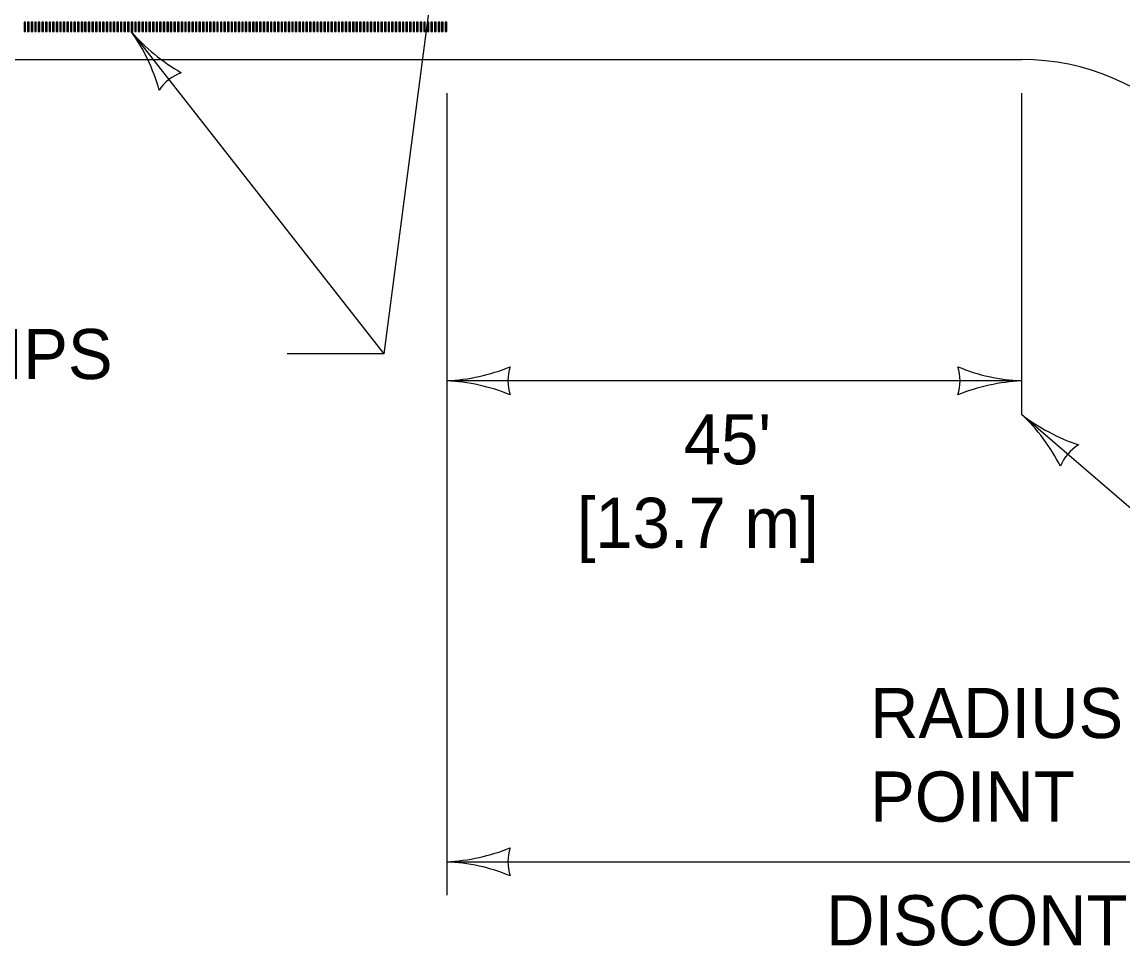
# Model space of a CAD drawing. Extents: x 49991.4 to 50021, y 49987.6 to 50011.4.
# Drawn here: x 50005.772 to 50007.091, y 49993.098 to 49994.204 of the extents above; entities that cross this region are included whole.
import ezdxf

# ---------------------------------------------------------------- set-up
doc = ezdxf.new("R2010")
doc.units = 0
for name, color, linetype in [('Level 1', 7, 'Continuous'), ('Level 2', 7, 'Continuous'), ('Level 3', 7, 'Continuous')]:
    doc.layers.add(name, color=color, linetype=linetype)

msp = doc.modelspace()

# ---------------------------------------------------------------- linework, layer by layer
at = {"layer": 'Level 1'}
msp.add_line((50005.3299, 49994.1595), (50006.9691, 49994.1595), dxfattribs=at)
for points in [[(50005.7764, 49994.2045), (50005.7745, 49994.2045), (50005.7745, 49994.1933), (50005.7764, 49994.1933)], [(50005.7807, 49994.2045), (50005.7787, 49994.2045), (50005.7787, 49994.1933), (50005.7807, 49994.1933)], [(50005.7849, 49994.2045), (50005.783, 49994.2045), (50005.783, 49994.1933), (50005.7849, 49994.1933)], [(50005.7892, 49994.2045), (50005.7873, 49994.2045), (50005.7873, 49994.1933), (50005.7892, 49994.1933)], [(50005.7935, 49994.2045), (50005.7916, 49994.2045), (50005.7916, 49994.1933), (50005.7935, 49994.1933)], [(50005.7977, 49994.2045), (50005.7959, 49994.2045), (50005.7959, 49994.1933), (50005.7977, 49994.1933)], [(50005.802, 49994.2045), (50005.8001, 49994.2045), (50005.8001, 49994.1933), (50005.802, 49994.1933)], [(50005.8063, 49994.2045), (50005.8044, 49994.2045), (50005.8044, 49994.1933), (50005.8063, 49994.1933)], [(50005.8106, 49994.2045), (50005.8087, 49994.2045), (50005.8087, 49994.1933), (50005.8106, 49994.1933)], [(50005.8149, 49994.2045), (50005.8129, 49994.2045), (50005.8129, 49994.1933), (50005.8149, 49994.1933)], [(50005.8191, 49994.2045), (50005.8172, 49994.2045), (50005.8172, 49994.1933), (50005.8191, 49994.1933)], [(50005.8234, 49994.2045), (50005.8215, 49994.2045), (50005.8215, 49994.1933), (50005.8234, 49994.1933)], [(50005.8277, 49994.2045), (50005.8258, 49994.2045), (50005.8258, 49994.1933), (50005.8277, 49994.1933)], [(50005.8319, 49994.2045), (50005.8301, 49994.2045), (50005.8301, 49994.1933), (50005.8319, 49994.1933)], [(50005.8362, 49994.2045), (50005.8343, 49994.2045), (50005.8343, 49994.1933), (50005.8362, 49994.1933)], [(50005.8405, 49994.2045), (50005.8386, 49994.2045), (50005.8386, 49994.1933), (50005.8405, 49994.1933)], [(50005.8448, 49994.2045), (50005.8429, 49994.2045), (50005.8429, 49994.1933), (50005.8448, 49994.1933)], [(50005.8491, 49994.2045), (50005.8471, 49994.2045), (50005.8471, 49994.1933), (50005.8491, 49994.1933)], [(50005.8533, 49994.2045), (50005.8514, 49994.2045), (50005.8514, 49994.1933), (50005.8533, 49994.1933)], [(50005.8576, 49994.2045), (50005.8557, 49994.2045), (50005.8557, 49994.1933), (50005.8576, 49994.1933)], [(50005.8619, 49994.2045), (50005.86, 49994.2045), (50005.86, 49994.1933), (50005.8619, 49994.1933)], [(50005.8661, 49994.2045), (50005.8643, 49994.2045), (50005.8643, 49994.1933), (50005.8661, 49994.1933)], [(50005.8704, 49994.2045), (50005.8685, 49994.2045), (50005.8685, 49994.1933), (50005.8704, 49994.1933)], [(50005.8747, 49994.2045), (50005.8728, 49994.2045), (50005.8728, 49994.1933), (50005.8747, 49994.1933)], [(50005.879, 49994.2045), (50005.8771, 49994.2045), (50005.8771, 49994.1933), (50005.879, 49994.1933)], [(50005.8833, 49994.2045), (50005.8813, 49994.2045), (50005.8813, 49994.1933), (50005.8833, 49994.1933)], [(50005.8875, 49994.2045), (50005.8856, 49994.2045), (50005.8856, 49994.1933), (50005.8875, 49994.1933)], [(50005.8918, 49994.2045), (50005.8899, 49994.2045), (50005.8899, 49994.1933), (50005.8918, 49994.1933)], [(50005.8961, 49994.2045), (50005.8942, 49994.2045), (50005.8942, 49994.1933), (50005.8961, 49994.1933)], [(50005.9003, 49994.2045), (50005.8985, 49994.2045), (50005.8985, 49994.1933), (50005.9003, 49994.1933)], [(50005.9046, 49994.2045), (50005.9027, 49994.2045), (50005.9027, 49994.1933), (50005.9046, 49994.1933)], [(50005.9089, 49994.2045), (50005.907, 49994.2045), (50005.907, 49994.1933), (50005.9089, 49994.1933)], [(50005.9132, 49994.2045), (50005.9113, 49994.2045), (50005.9113, 49994.1933), (50005.9132, 49994.1933)], [(50005.9175, 49994.2045), (50005.9155, 49994.2045), (50005.9155, 49994.1933), (50005.9175, 49994.1933)], [(50005.9217, 49994.2045), (50005.9198, 49994.2045), (50005.9198, 49994.1933), (50005.9217, 49994.1933)], [(50005.926, 49994.2045), (50005.9241, 49994.2045), (50005.9241, 49994.1933), (50005.926, 49994.1933)], [(50005.9303, 49994.2045), (50005.9284, 49994.2045), (50005.9284, 49994.1933), (50005.9303, 49994.1933)], [(50005.9345, 49994.2045), (50005.9327, 49994.2045), (50005.9327, 49994.1933), (50005.9345, 49994.1933)], [(50005.9388, 49994.2045), (50005.9369, 49994.2045), (50005.9369, 49994.1933), (50005.9388, 49994.1933)], [(50005.9431, 49994.2045), (50005.9412, 49994.2045), (50005.9412, 49994.1933), (50005.9431, 49994.1933)], [(50005.9474, 49994.2045), (50005.9455, 49994.2045), (50005.9455, 49994.1933), (50005.9474, 49994.1933)], [(50005.9517, 49994.2045), (50005.9497, 49994.2045), (50005.9497, 49994.1933), (50005.9517, 49994.1933)], [(50005.9559, 49994.2045), (50005.954, 49994.2045), (50005.954, 49994.1933), (50005.9559, 49994.1933)], [(50005.9602, 49994.2045), (50005.9583, 49994.2045), (50005.9583, 49994.1933), (50005.9602, 49994.1933)], [(50005.9645, 49994.2045), (50005.9626, 49994.2045), (50005.9626, 49994.1933), (50005.9645, 49994.1933)], [(50005.9687, 49994.2045), (50005.9669, 49994.2045), (50005.9669, 49994.1933), (50005.9687, 49994.1933)], [(50005.973, 49994.2045), (50005.9711, 49994.2045), (50005.9711, 49994.1933), (50005.973, 49994.1933)], [(50005.9773, 49994.2045), (50005.9754, 49994.2045), (50005.9754, 49994.1933), (50005.9773, 49994.1933)], [(50005.9816, 49994.2045), (50005.9797, 49994.2045), (50005.9797, 49994.1933), (50005.9816, 49994.1933)], [(50005.9859, 49994.2045), (50005.9839, 49994.2045), (50005.9839, 49994.1933), (50005.9859, 49994.1933)], [(50005.9901, 49994.2045), (50005.9882, 49994.2045), (50005.9882, 49994.1933), (50005.9901, 49994.1933)], [(50005.9944, 49994.2045), (50005.9925, 49994.2045), (50005.9925, 49994.1933), (50005.9944, 49994.1933)], [(50005.9987, 49994.2045), (50005.9968, 49994.2045), (50005.9968, 49994.1933), (50005.9987, 49994.1933)], [(50006.0029, 49994.2045), (50006.0011, 49994.2045), (50006.0011, 49994.1933), (50006.0029, 49994.1933)], [(50006.0072, 49994.2045), (50006.0053, 49994.2045), (50006.0053, 49994.1933), (50006.0072, 49994.1933)], [(50006.0115, 49994.2045), (50006.0096, 49994.2045), (50006.0096, 49994.1933), (50006.0115, 49994.1933)], [(50006.0158, 49994.2045), (50006.0139, 49994.2045), (50006.0139, 49994.1933), (50006.0158, 49994.1933)], [(50006.0201, 49994.2045), (50006.0181, 49994.2045), (50006.0181, 49994.1933), (50006.0201, 49994.1933)], [(50006.0243, 49994.2045), (50006.0224, 49994.2045), (50006.0224, 49994.1933), (50006.0243, 49994.1933)], [(50006.0286, 49994.2045), (50006.0267, 49994.2045), (50006.0267, 49994.1933), (50006.0286, 49994.1933)], [(50006.0329, 49994.2045), (50006.031, 49994.2045), (50006.031, 49994.1933), (50006.0329, 49994.1933)], [(50006.0371, 49994.2045), (50006.0353, 49994.2045), (50006.0353, 49994.1933), (50006.0371, 49994.1933)], [(50006.0414, 49994.2045), (50006.0395, 49994.2045), (50006.0395, 49994.1933), (50006.0414, 49994.1933)], [(50006.0457, 49994.2045), (50006.0438, 49994.2045), (50006.0438, 49994.1933), (50006.0457, 49994.1933)], [(50006.05, 49994.2045), (50006.0481, 49994.2045), (50006.0481, 49994.1933), (50006.05, 49994.1933)], [(50006.0543, 49994.2045), (50006.0523, 49994.2045), (50006.0523, 49994.1933), (50006.0543, 49994.1933)], [(50006.0585, 49994.2045), (50006.0566, 49994.2045), (50006.0566, 49994.1933), (50006.0585, 49994.1933)], [(50006.0628, 49994.2045), (50006.0609, 49994.2045), (50006.0609, 49994.1933), (50006.0628, 49994.1933)], [(50006.0671, 49994.2045), (50006.0652, 49994.2045), (50006.0652, 49994.1933), (50006.0671, 49994.1933)], [(50006.0713, 49994.2045), (50006.0695, 49994.2045), (50006.0695, 49994.1933), (50006.0713, 49994.1933)], [(50006.0756, 49994.2045), (50006.0737, 49994.2045), (50006.0737, 49994.1933), (50006.0756, 49994.1933)], [(50006.0799, 49994.2045), (50006.078, 49994.2045), (50006.078, 49994.1933), (50006.0799, 49994.1933)], [(50006.0842, 49994.2045), (50006.0823, 49994.2045), (50006.0823, 49994.1933), (50006.0842, 49994.1933)], [(50006.0885, 49994.2045), (50006.0865, 49994.2045), (50006.0865, 49994.1933), (50006.0885, 49994.1933)], [(50006.0927, 49994.2045), (50006.0908, 49994.2045), (50006.0908, 49994.1933), (50006.0927, 49994.1933)], [(50006.097, 49994.2045), (50006.0951, 49994.2045), (50006.0951, 49994.1933), (50006.097, 49994.1933)], [(50006.1013, 49994.2045), (50006.0994, 49994.2045), (50006.0994, 49994.1933), (50006.1013, 49994.1933)], [(50006.1055, 49994.2045), (50006.1037, 49994.2045), (50006.1037, 49994.1933), (50006.1055, 49994.1933)], [(50006.1098, 49994.2045), (50006.1079, 49994.2045), (50006.1079, 49994.1933), (50006.1098, 49994.1933)], [(50006.1141, 49994.2045), (50006.1122, 49994.2045), (50006.1122, 49994.1933), (50006.1141, 49994.1933)], [(50006.1184, 49994.2045), (50006.1165, 49994.2045), (50006.1165, 49994.1933), (50006.1184, 49994.1933)], [(50006.1227, 49994.2045), (50006.1207, 49994.2045), (50006.1207, 49994.1933), (50006.1227, 49994.1933)], [(50006.1269, 49994.2045), (50006.125, 49994.2045), (50006.125, 49994.1933), (50006.1269, 49994.1933)], [(50006.1312, 49994.2045), (50006.1293, 49994.2045), (50006.1293, 49994.1933), (50006.1312, 49994.1933)], [(50006.1355, 49994.2045), (50006.1335, 49994.2045), (50006.1335, 49994.1933), (50006.1355, 49994.1933)], [(50006.1397, 49994.2045), (50006.1378, 49994.2045), (50006.1378, 49994.1933), (50006.1397, 49994.1933)], [(50006.144, 49994.2045), (50006.1421, 49994.2045), (50006.1421, 49994.1933), (50006.144, 49994.1933)], [(50006.1483, 49994.2045), (50006.1464, 49994.2045), (50006.1464, 49994.1933), (50006.1483, 49994.1933)], [(50006.1525, 49994.2045), (50006.1507, 49994.2045), (50006.1507, 49994.1933), (50006.1525, 49994.1933)], [(50006.1568, 49994.2045), (50006.1549, 49994.2045), (50006.1549, 49994.1933), (50006.1568, 49994.1933)], [(50006.1611, 49994.2045), (50006.1592, 49994.2045), (50006.1592, 49994.1933), (50006.1611, 49994.1933)], [(50006.1654, 49994.2045), (50006.1635, 49994.2045), (50006.1635, 49994.1933), (50006.1654, 49994.1933)], [(50006.1697, 49994.2045), (50006.1677, 49994.2045), (50006.1677, 49994.1933), (50006.1697, 49994.1933)], [(50006.1739, 49994.2045), (50006.172, 49994.2045), (50006.172, 49994.1933), (50006.1739, 49994.1933)], [(50006.1782, 49994.2045), (50006.1763, 49994.2045), (50006.1763, 49994.1933), (50006.1782, 49994.1933)], [(50006.1825, 49994.2045), (50006.1806, 49994.2045), (50006.1806, 49994.1933), (50006.1825, 49994.1933)], [(50006.1867, 49994.2045), (50006.1849, 49994.2045), (50006.1849, 49994.1933), (50006.1867, 49994.1933)], [(50006.191, 49994.2045), (50006.1891, 49994.2045), (50006.1891, 49994.1933), (50006.191, 49994.1933)], [(50006.1953, 49994.2045), (50006.1934, 49994.2045), (50006.1934, 49994.1933), (50006.1953, 49994.1933)], [(50006.1996, 49994.2045), (50006.1977, 49994.2045), (50006.1977, 49994.1933), (50006.1996, 49994.1933)], [(50006.2039, 49994.2045), (50006.2019, 49994.2045), (50006.2019, 49994.1933), (50006.2039, 49994.1933)], [(50006.2081, 49994.2045), (50006.2062, 49994.2045), (50006.2062, 49994.1933), (50006.2081, 49994.1933)], [(50006.2124, 49994.2045), (50006.2105, 49994.2045), (50006.2105, 49994.1933), (50006.2124, 49994.1933)], [(50006.2167, 49994.2045), (50006.2148, 49994.2045), (50006.2148, 49994.1933), (50006.2167, 49994.1933)], [(50006.2209, 49994.2045), (50006.2191, 49994.2045), (50006.2191, 49994.1933), (50006.2209, 49994.1933)], [(50006.2252, 49994.2045), (50006.2233, 49994.2045), (50006.2233, 49994.1933), (50006.2252, 49994.1933)], [(50006.2295, 49994.2045), (50006.2276, 49994.2045), (50006.2276, 49994.1933), (50006.2295, 49994.1933)], [(50006.2338, 49994.2045), (50006.2319, 49994.2045), (50006.2319, 49994.1933), (50006.2338, 49994.1933)], [(50006.2381, 49994.2045), (50006.2361, 49994.2045), (50006.2361, 49994.1933), (50006.2381, 49994.1933)], [(50006.2423, 49994.2045), (50006.2404, 49994.2045), (50006.2404, 49994.1933), (50006.2423, 49994.1933)], [(50006.2466, 49994.2045), (50006.2447, 49994.2045), (50006.2447, 49994.1933), (50006.2466, 49994.1933)], [(50006.2509, 49994.2045), (50006.249, 49994.2045), (50006.249, 49994.1933), (50006.2509, 49994.1933)], [(50006.2551, 49994.2045), (50006.2533, 49994.2045), (50006.2533, 49994.1933), (50006.2551, 49994.1933)], [(50006.2594, 49994.2045), (50006.2575, 49994.2045), (50006.2575, 49994.1933), (50006.2594, 49994.1933)], [(50006.2637, 49994.2045), (50006.2618, 49994.2045), (50006.2618, 49994.1933), (50006.2637, 49994.1933)], [(50006.268, 49994.2045), (50006.2661, 49994.2045), (50006.2661, 49994.1933), (50006.268, 49994.1933)], [(50006.2723, 49994.2045), (50006.2703, 49994.2045), (50006.2703, 49994.1933), (50006.2723, 49994.1933)], [(50006.2765, 49994.2045), (50006.2746, 49994.2045), (50006.2746, 49994.1933), (50006.2765, 49994.1933)], [(50006.2807, 49994.2045), (50006.2788, 49994.2045), (50006.2788, 49994.1933), (50006.2807, 49994.1933)]]:
    msp.add_lwpolyline(points, close=True, dxfattribs=at)
msp.add_arc((50006.9691, 49993.8783), 0.2813, 359.9898, 89.9898, dxfattribs=at)
at = {"layer": 'Level 3'}
for p, q in [((50006.2931, 49994.4745), (50006.2053, 49993.807)), ((50005.9027, 49994.1933), (50006.2053, 49993.807)), ((50006.2807, 49994.1195), (50006.2807, 49993.159)), ((50006.969, 49994.1195), (50006.969, 49993.7349)), ((50006.2053, 49993.807), (50006.0898, 49993.807)), ((50006.969, 49993.7749), (50006.2807, 49993.7749)), ((50006.969, 49993.7349), (50007.3853, 49993.3771)), ((50006.2807, 49993.199), (50008.1872, 49993.199))]:
    msp.add_line(p, q, dxfattribs=at)
for centre, radius, start, end in [((50005.7222, 49994.0635), 0.2223, 15.544, 35.7275), ((50006.0787, 49994.3459), 0.233, 220.9153, 240.1652), ((50005.9817, 49994.0924), 0.0548, 110.2268, 145.9492), ((50006.2692, 49994.0076), 0.233, 272.8273, 292.0772), ((50006.4089, 49993.7749), 0.0548, 162.1388, 197.8612), ((50006.9782, 49993.997), 0.2223, 247.456, 267.6395), ((50006.8408, 49993.7749), 0.0548, 342.1388, 17.8612), ((50006.2715, 49993.5527), 0.2223, 67.456, 87.6395), ((50006.9805, 49993.5421), 0.233, 92.8273, 112.0772), ((50006.8173, 49993.5724), 0.2223, 26.7784, 46.9619), ((50007.112, 49993.9189), 0.233, 232.1497, 251.3996), ((50007.0662, 49993.6513), 0.0548, 121.4612, 157.1836), ((50006.2692, 49993.4317), 0.233, 272.8273, 292.0772), ((50006.4089, 49993.199), 0.0548, 162.1388, 197.8612), ((50006.2715, 49992.9768), 0.2223, 67.456, 87.6395)]:
    msp.add_arc(centre, radius, start, end, dxfattribs=at)

# ---------------------------------------------------------------- texts
at = {"layer": 'Level 2'}
for s, p in [('INTERMITTENT RUMBLE STRIPS', (50004.6235, 49993.777)), ('RADIUS', (50006.7878, 49993.3471)), ('POINT', (50006.7878, 49993.2471))]:
    msp.add_text(s, height=0.06, rotation=359.9999, dxfattribs=at).set_placement(p)
for s, p in [("45'", (50006.5647, 49993.6749)), ('[13.7 m]', (50006.4365, 49993.5749)), ('DISCONTINUE RUMBLE', (50006.7351, 49993.099))]:
    msp.add_text(s, height=0.06, dxfattribs=at).set_placement(p)

doc.saveas('drawing.dxf')
